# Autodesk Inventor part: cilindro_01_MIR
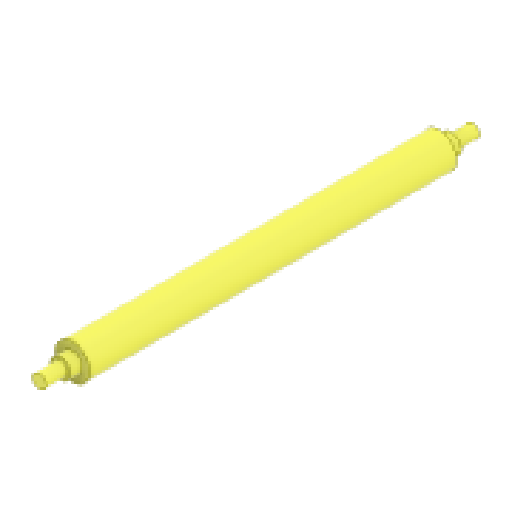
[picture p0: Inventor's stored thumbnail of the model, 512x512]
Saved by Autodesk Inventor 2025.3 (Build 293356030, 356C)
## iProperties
Created: 2025-09
Part Number: cilindro_01_MIR
Material: Plastica ABS
Document SubType Name: Modeling
Designer: R5800u
Density: 1.06 g/cm^3
Appearance: Liscia - Bianco
Author: R5800u
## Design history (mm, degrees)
derived "cilindro_01.ipt"
  sketch "Schizzo1"
    geometry: C1 r 10.5 at (0, 0) reference; 1 further point
  sketch "Schizzo2"
    geometry: C1 r 4 at (0, 0) reference; 1 further point
  sketch "Schizzo3"
    geometry: C1 r 4 at (0, 0) reference; 1 further point
  sketch "Schizzo4"
    geometry: C1 r 4 at (0, 0) reference; C2 r 6 at (0, 0) reference; 1 further point
  sketch "Schizzo5"
    geometry: C1 r 4 at (0, 0) reference; 1 further point
  sketch "Schizzo6"
    geometry: C1 r 4 at (0, 0) reference; C2 r 6 at (0, 0) reference; 1 further point
  node "Piano di lavoro1"
  node "Piano di lavoro2"
sketch "Schizzo7"
  geometry: C1 r 4 at (0, 0); 1 further point
  constraints: 1 centre point, 1 coincident
  dimensions: "d1" = 8 diameter of C1
extrude "Estrusione1" cut sketch "Schizzo7" distance "d2" = 10; taper "d3" = 0 deg
feature "Solido1::cilindro_01.ipt"
tag "Lavorazione contrassegno1"
node "Solido1"
